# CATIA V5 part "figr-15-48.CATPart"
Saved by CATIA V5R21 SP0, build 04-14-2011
Part number: Part1
Bounding box of the stored display mesh (mm): x 0 to 69.121, y -21.475 to 20.775, z 0 to 47.185
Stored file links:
  D:\CATIA V5R21 E-RESOURCES\CATIA-V5R21\catia-v5r21-Prts\c15_catia_v5r21_prt\figr-15-48.CATPart
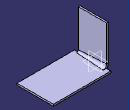
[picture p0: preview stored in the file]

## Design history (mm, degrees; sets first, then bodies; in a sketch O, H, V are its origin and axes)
SheetMetalParameters1: Thickness 2, BendRadius 4, KFactor 0.400515 {= log(min(100,max(20*SheetMetalParameters1.BendRadius,SheetMetalParameters1.Thickness)/SheetMetalParameters1.Thickness))/log(100)/2}, ReliefRadialLength 1, ReliefAxialLength 2, MinimumBendRadius 0
Body1 (main body)
  Sketch1 on xy-plane, origin (0, 0, 0), H (1, 0, 0), V (0, 1, 0)
    line L1 (2.4998, 20.7748) -> (69.1212, 20.7748)
    line L2 (69.1212, 20.7748) -> (69.1212, -21.4753)
    line L3 (69.1212, -21.4753) -> (2.4998, -21.4753)
    line L4 (2.4998, -21.4753) -> (2.4998, 20.7748)
    horizontal: L1 H, L3 H
    vertical: L2 V, L4 V
  Wall1: Thickness 2, Profile Sketch1
  Sketch2 on yz-plane, origin (0, 0, 0), H (0, 1, 0), V (0, 0, 1)
    line L1 (-17.3994, 47.1851) -> (15.4124, 47.1851)
    line L2 (15.4124, 47.1851) -> (15.4124, 3.5135)
    line L3 (15.4124, 3.5135) -> (-17.3994, 3.5135)
    line L4 (-17.3994, 3.5135) -> (-17.3994, 47.1851)
    horizontal: L1 H, L3 H
    vertical: L2 V, L4 V
  Wall2: Thickness 2, Profile Sketch2
  d_Bend1: Bend_Thickness 2, Bend_KFactor 0.36928 {= log(min(100,max(20*d_Bend1.Bend_KFactorRadius,SheetMetalParameters1.Thickness)/SheetMetalParameters1.Thickness))/log(100)/2}, Bend_KFactorRadius 3 {= ( d_Bend1.ConicalBendSurf_FirstRadius + d_Bend1.ConicalBendSurf_SecondRadius ) / 2.0}, Bend_FirstSupport Wall1, Bend_SecondSupport Wall2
